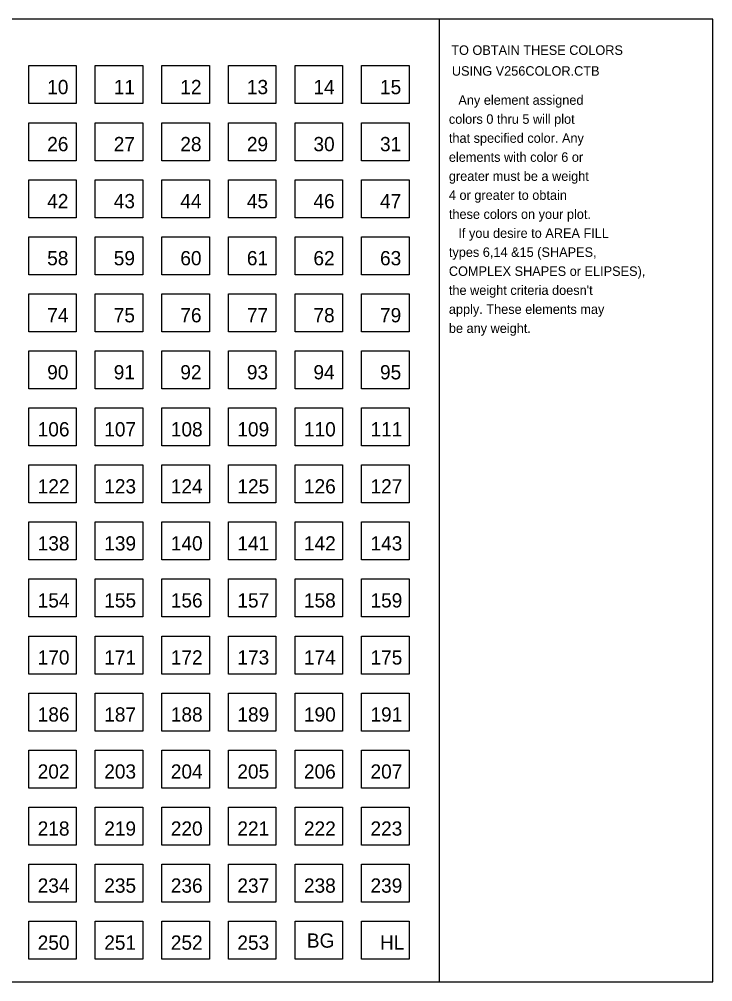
# Model space of a CAD drawing. Extents: x 11193 to 12507, y 10092 to 10555.
# Drawn here: x 12215.3 to 12507, y 10137.6 to 10542.6 of the extents above; entities that cross this region are included whole.
import ezdxf

# ---------------------------------------------------------------- set-up
doc = ezdxf.new("R2010")
doc.units = 0
for name, color, linetype in [('Level 1', 7, 'Continuous'), ('Level 3', 7, 'Continuous'), ('Level 62', 7, 'Continuous'), ('Level 63', 7, 'Continuous')]:
    doc.layers.add(name, color=color, linetype=linetype)

msp = doc.modelspace()

# ---------------------------------------------------------------- linework, layer by layer
at = {"layer": 'Level 3'}
msp.add_line((12391.98, 10137.56), (12391.98, 10542.56), dxfattribs=at)
msp.add_lwpolyline([(11926.98, 10137.56), (12506.98, 10137.56), (12506.98, 10542.56), (11926.98, 10542.56), (11926.98, 10137.56)], dxfattribs=at)
for points in [[(12219.26, 10507.04), (12219.26, 10523.04), (12239.26, 10523.04), (12239.26, 10507.04)], [(12247.26, 10507.04), (12247.26, 10523.04), (12267.26, 10523.04), (12267.26, 10507.04)], [(12275.26, 10507.04), (12275.26, 10523.04), (12295.26, 10523.04), (12295.26, 10507.04)], [(12303.26, 10507.04), (12303.26, 10523.04), (12323.26, 10523.04), (12323.26, 10507.04)], [(12331.26, 10507.04), (12331.26, 10523.04), (12351.26, 10523.04), (12351.26, 10507.04)], [(12359.26, 10507.04), (12359.26, 10523.04), (12379.26, 10523.04), (12379.26, 10507.04)], [(12219.26, 10483.04), (12219.26, 10499.04), (12239.26, 10499.04), (12239.26, 10483.04)], [(12247.26, 10483.04), (12247.26, 10499.04), (12267.26, 10499.04), (12267.26, 10483.04)], [(12275.26, 10483.04), (12275.26, 10499.04), (12295.26, 10499.04), (12295.26, 10483.04)], [(12303.26, 10483.04), (12303.26, 10499.04), (12323.26, 10499.04), (12323.26, 10483.04)], [(12331.26, 10483.04), (12331.26, 10499.04), (12351.26, 10499.04), (12351.26, 10483.04)], [(12359.26, 10483.04), (12359.26, 10499.04), (12379.26, 10499.04), (12379.26, 10483.04)], [(12219.26, 10459.04), (12219.26, 10475.04), (12239.26, 10475.04), (12239.26, 10459.04)], [(12247.26, 10459.04), (12247.26, 10475.04), (12267.26, 10475.04), (12267.26, 10459.04)], [(12275.26, 10459.04), (12275.26, 10475.04), (12295.26, 10475.04), (12295.26, 10459.04)], [(12303.26, 10459.04), (12303.26, 10475.04), (12323.26, 10475.04), (12323.26, 10459.04)], [(12331.26, 10459.04), (12331.26, 10475.04), (12351.26, 10475.04), (12351.26, 10459.04)], [(12359.26, 10459.04), (12359.26, 10475.04), (12379.26, 10475.04), (12379.26, 10459.04)], [(12219.26, 10435.04), (12219.26, 10451.04), (12239.26, 10451.04), (12239.26, 10435.04)], [(12247.26, 10435.04), (12247.26, 10451.04), (12267.26, 10451.04), (12267.26, 10435.04)], [(12275.26, 10435.04), (12275.26, 10451.04), (12295.26, 10451.04), (12295.26, 10435.04)], [(12303.26, 10435.04), (12303.26, 10451.04), (12323.26, 10451.04), (12323.26, 10435.04)], [(12331.26, 10435.04), (12331.26, 10451.04), (12351.26, 10451.04), (12351.26, 10435.04)], [(12359.26, 10435.04), (12359.26, 10451.04), (12379.26, 10451.04), (12379.26, 10435.04)], [(12219.26, 10411.04), (12219.26, 10427.04), (12239.26, 10427.04), (12239.26, 10411.04)], [(12247.26, 10411.04), (12247.26, 10427.04), (12267.26, 10427.04), (12267.26, 10411.04)], [(12275.26, 10411.04), (12275.26, 10427.04), (12295.26, 10427.04), (12295.26, 10411.04)], [(12303.26, 10411.04), (12303.26, 10427.04), (12323.26, 10427.04), (12323.26, 10411.04)], [(12331.26, 10411.04), (12331.26, 10427.04), (12351.26, 10427.04), (12351.26, 10411.04)], [(12359.26, 10411.04), (12359.26, 10427.04), (12379.26, 10427.04), (12379.26, 10411.04)], [(12219.26, 10387.04), (12219.26, 10403.04), (12239.26, 10403.04), (12239.26, 10387.04)], [(12247.26, 10387.04), (12247.26, 10403.04), (12267.26, 10403.04), (12267.26, 10387.04)], [(12275.26, 10387.04), (12275.26, 10403.04), (12295.26, 10403.04), (12295.26, 10387.04)], [(12303.26, 10387.04), (12303.26, 10403.04), (12323.26, 10403.04), (12323.26, 10387.04)], [(12331.26, 10387.04), (12331.26, 10403.04), (12351.26, 10403.04), (12351.26, 10387.04)], [(12359.26, 10387.04), (12359.26, 10403.04), (12379.26, 10403.04), (12379.26, 10387.04)], [(12219.26, 10363.04), (12219.26, 10379.04), (12239.26, 10379.04), (12239.26, 10363.04)], [(12247.26, 10363.04), (12247.26, 10379.04), (12267.26, 10379.04), (12267.26, 10363.04)], [(12275.26, 10363.04), (12275.26, 10379.04), (12295.26, 10379.04), (12295.26, 10363.04)], [(12303.26, 10363.04), (12303.26, 10379.04), (12323.26, 10379.04), (12323.26, 10363.04)], [(12331.26, 10363.04), (12331.26, 10379.04), (12351.26, 10379.04), (12351.26, 10363.04)], [(12359.26, 10363.04), (12359.26, 10379.04), (12379.26, 10379.04), (12379.26, 10363.04)], [(12219.26, 10339.04), (12219.26, 10355.04), (12239.26, 10355.04), (12239.26, 10339.04)], [(12247.26, 10339.04), (12247.26, 10355.04), (12267.26, 10355.04), (12267.26, 10339.04)], [(12275.26, 10339.04), (12275.26, 10355.04), (12295.26, 10355.04), (12295.26, 10339.04)], [(12303.26, 10339.04), (12303.26, 10355.04), (12323.26, 10355.04), (12323.26, 10339.04)], [(12331.26, 10339.04), (12331.26, 10355.04), (12351.26, 10355.04), (12351.26, 10339.04)], [(12359.26, 10339.04), (12359.26, 10355.04), (12379.26, 10355.04), (12379.26, 10339.04)], [(12219.26, 10315.04), (12219.26, 10331.04), (12239.26, 10331.04), (12239.26, 10315.04)], [(12247.26, 10315.04), (12247.26, 10331.04), (12267.26, 10331.04), (12267.26, 10315.04)], [(12275.26, 10315.04), (12275.26, 10331.04), (12295.26, 10331.04), (12295.26, 10315.04)], [(12303.26, 10315.04), (12303.26, 10331.04), (12323.26, 10331.04), (12323.26, 10315.04)], [(12331.26, 10315.04), (12331.26, 10331.04), (12351.26, 10331.04), (12351.26, 10315.04)], [(12359.26, 10315.04), (12359.26, 10331.04), (12379.26, 10331.04), (12379.26, 10315.04)], [(12219.26, 10291.04), (12219.26, 10307.04), (12239.26, 10307.04), (12239.26, 10291.04)], [(12247.26, 10291.04), (12247.26, 10307.04), (12267.26, 10307.04), (12267.26, 10291.04)], [(12275.26, 10291.04), (12275.26, 10307.04), (12295.26, 10307.04), (12295.26, 10291.04)], [(12303.26, 10291.04), (12303.26, 10307.04), (12323.26, 10307.04), (12323.26, 10291.04)], [(12331.26, 10291.04), (12331.26, 10307.04), (12351.26, 10307.04), (12351.26, 10291.04)], [(12359.26, 10291.04), (12359.26, 10307.04), (12379.26, 10307.04), (12379.26, 10291.04)], [(12219.26, 10267.04), (12219.26, 10283.04), (12239.26, 10283.04), (12239.26, 10267.04)], [(12247.26, 10267.04), (12247.26, 10283.04), (12267.26, 10283.04), (12267.26, 10267.04)], [(12275.26, 10267.04), (12275.26, 10283.04), (12295.26, 10283.04), (12295.26, 10267.04)], [(12303.26, 10267.04), (12303.26, 10283.04), (12323.26, 10283.04), (12323.26, 10267.04)], [(12331.26, 10267.04), (12331.26, 10283.04), (12351.26, 10283.04), (12351.26, 10267.04)], [(12359.26, 10267.04), (12359.26, 10283.04), (12379.26, 10283.04), (12379.26, 10267.04)], [(12219.26, 10243.04), (12219.26, 10259.04), (12239.26, 10259.04), (12239.26, 10243.04)], [(12247.26, 10243.04), (12247.26, 10259.04), (12267.26, 10259.04), (12267.26, 10243.04)], [(12275.26, 10243.04), (12275.26, 10259.04), (12295.26, 10259.04), (12295.26, 10243.04)], [(12303.26, 10243.04), (12303.26, 10259.04), (12323.26, 10259.04), (12323.26, 10243.04)], [(12331.26, 10243.04), (12331.26, 10259.04), (12351.26, 10259.04), (12351.26, 10243.04)], [(12359.26, 10243.04), (12359.26, 10259.04), (12379.26, 10259.04), (12379.26, 10243.04)], [(12219.26, 10219.04), (12219.26, 10235.04), (12239.26, 10235.04), (12239.26, 10219.04)], [(12247.26, 10219.04), (12247.26, 10235.04), (12267.26, 10235.04), (12267.26, 10219.04)], [(12275.26, 10219.04), (12275.26, 10235.04), (12295.26, 10235.04), (12295.26, 10219.04)], [(12303.26, 10219.04), (12303.26, 10235.04), (12323.26, 10235.04), (12323.26, 10219.04)], [(12331.26, 10219.04), (12331.26, 10235.04), (12351.26, 10235.04), (12351.26, 10219.04)], [(12359.26, 10219.04), (12359.26, 10235.04), (12379.26, 10235.04), (12379.26, 10219.04)], [(12219.26, 10195.04), (12219.26, 10211.04), (12239.26, 10211.04), (12239.26, 10195.04)], [(12247.26, 10195.04), (12247.26, 10211.04), (12267.26, 10211.04), (12267.26, 10195.04)], [(12275.26, 10195.04), (12275.26, 10211.04), (12295.26, 10211.04), (12295.26, 10195.04)], [(12303.26, 10195.04), (12303.26, 10211.04), (12323.26, 10211.04), (12323.26, 10195.04)], [(12331.26, 10195.04), (12331.26, 10211.04), (12351.26, 10211.04), (12351.26, 10195.04)], [(12359.26, 10195.04), (12359.26, 10211.04), (12379.26, 10211.04), (12379.26, 10195.04)], [(12219.26, 10171.04), (12219.26, 10187.04), (12239.26, 10187.04), (12239.26, 10171.04)], [(12247.26, 10171.04), (12247.26, 10187.04), (12267.26, 10187.04), (12267.26, 10171.04)], [(12275.26, 10171.04), (12275.26, 10187.04), (12295.26, 10187.04), (12295.26, 10171.04)], [(12303.26, 10171.04), (12303.26, 10187.04), (12323.26, 10187.04), (12323.26, 10171.04)], [(12331.26, 10171.04), (12331.26, 10187.04), (12351.26, 10187.04), (12351.26, 10171.04)], [(12359.26, 10171.04), (12359.26, 10187.04), (12379.26, 10187.04), (12379.26, 10171.04)], [(12219.26, 10147.04), (12219.26, 10163.04), (12239.26, 10163.04), (12239.26, 10147.04)], [(12247.26, 10147.04), (12247.26, 10163.04), (12267.26, 10163.04), (12267.26, 10147.04)], [(12275.26, 10147.04), (12275.26, 10163.04), (12295.26, 10163.04), (12295.26, 10147.04)], [(12303.26, 10147.04), (12303.26, 10163.04), (12323.26, 10163.04), (12323.26, 10147.04)]]:
    msp.add_lwpolyline(points, close=True, dxfattribs=at)
at = {"layer": 'Level 63'}
for points in [[(12219.26, 10507.04), (12219.26, 10523.04), (12239.26, 10523.04), (12239.26, 10507.04)], [(12247.26, 10507.04), (12247.26, 10523.04), (12267.26, 10523.04), (12267.26, 10507.04)], [(12275.26, 10507.04), (12275.26, 10523.04), (12295.26, 10523.04), (12295.26, 10507.04)], [(12303.26, 10507.04), (12303.26, 10523.04), (12323.26, 10523.04), (12323.26, 10507.04)], [(12331.26, 10507.04), (12331.26, 10523.04), (12351.26, 10523.04), (12351.26, 10507.04)], [(12359.26, 10507.04), (12359.26, 10523.04), (12379.26, 10523.04), (12379.26, 10507.04)], [(12219.26, 10483.04), (12219.26, 10499.04), (12239.26, 10499.04), (12239.26, 10483.04)], [(12247.26, 10483.04), (12247.26, 10499.04), (12267.26, 10499.04), (12267.26, 10483.04)], [(12275.26, 10483.04), (12275.26, 10499.04), (12295.26, 10499.04), (12295.26, 10483.04)], [(12303.26, 10483.04), (12303.26, 10499.04), (12323.26, 10499.04), (12323.26, 10483.04)], [(12331.26, 10483.04), (12331.26, 10499.04), (12351.26, 10499.04), (12351.26, 10483.04)], [(12359.26, 10483.04), (12359.26, 10499.04), (12379.26, 10499.04), (12379.26, 10483.04)], [(12219.26, 10459.04), (12219.26, 10475.04), (12239.26, 10475.04), (12239.26, 10459.04)], [(12247.26, 10459.04), (12247.26, 10475.04), (12267.26, 10475.04), (12267.26, 10459.04)], [(12275.26, 10459.04), (12275.26, 10475.04), (12295.26, 10475.04), (12295.26, 10459.04)], [(12303.26, 10459.04), (12303.26, 10475.04), (12323.26, 10475.04), (12323.26, 10459.04)], [(12331.26, 10459.04), (12331.26, 10475.04), (12351.26, 10475.04), (12351.26, 10459.04)], [(12359.26, 10459.04), (12359.26, 10475.04), (12379.26, 10475.04), (12379.26, 10459.04)], [(12219.26, 10435.04), (12219.26, 10451.04), (12239.26, 10451.04), (12239.26, 10435.04)], [(12247.26, 10435.04), (12247.26, 10451.04), (12267.26, 10451.04), (12267.26, 10435.04)], [(12275.26, 10435.04), (12275.26, 10451.04), (12295.26, 10451.04), (12295.26, 10435.04)], [(12303.26, 10435.04), (12303.26, 10451.04), (12323.26, 10451.04), (12323.26, 10435.04)], [(12331.26, 10435.04), (12331.26, 10451.04), (12351.26, 10451.04), (12351.26, 10435.04)], [(12359.26, 10435.04), (12359.26, 10451.04), (12379.26, 10451.04), (12379.26, 10435.04)], [(12219.26, 10411.04), (12219.26, 10427.04), (12239.26, 10427.04), (12239.26, 10411.04)], [(12247.26, 10411.04), (12247.26, 10427.04), (12267.26, 10427.04), (12267.26, 10411.04)], [(12275.26, 10411.04), (12275.26, 10427.04), (12295.26, 10427.04), (12295.26, 10411.04)], [(12303.26, 10411.04), (12303.26, 10427.04), (12323.26, 10427.04), (12323.26, 10411.04)], [(12331.26, 10411.04), (12331.26, 10427.04), (12351.26, 10427.04), (12351.26, 10411.04)], [(12359.26, 10411.04), (12359.26, 10427.04), (12379.26, 10427.04), (12379.26, 10411.04)], [(12219.26, 10387.04), (12219.26, 10403.04), (12239.26, 10403.04), (12239.26, 10387.04)], [(12247.26, 10387.04), (12247.26, 10403.04), (12267.26, 10403.04), (12267.26, 10387.04)], [(12275.26, 10387.04), (12275.26, 10403.04), (12295.26, 10403.04), (12295.26, 10387.04)], [(12303.26, 10387.04), (12303.26, 10403.04), (12323.26, 10403.04), (12323.26, 10387.04)], [(12331.26, 10387.04), (12331.26, 10403.04), (12351.26, 10403.04), (12351.26, 10387.04)], [(12359.26, 10387.04), (12359.26, 10403.04), (12379.26, 10403.04), (12379.26, 10387.04)], [(12219.26, 10363.04), (12219.26, 10379.04), (12239.26, 10379.04), (12239.26, 10363.04)], [(12247.26, 10363.04), (12247.26, 10379.04), (12267.26, 10379.04), (12267.26, 10363.04)], [(12275.26, 10363.04), (12275.26, 10379.04), (12295.26, 10379.04), (12295.26, 10363.04)], [(12303.26, 10363.04), (12303.26, 10379.04), (12323.26, 10379.04), (12323.26, 10363.04)], [(12331.26, 10363.04), (12331.26, 10379.04), (12351.26, 10379.04), (12351.26, 10363.04)], [(12359.26, 10363.04), (12359.26, 10379.04), (12379.26, 10379.04), (12379.26, 10363.04)], [(12219.26, 10339.04), (12219.26, 10355.04), (12239.26, 10355.04), (12239.26, 10339.04)], [(12247.26, 10339.04), (12247.26, 10355.04), (12267.26, 10355.04), (12267.26, 10339.04)], [(12275.26, 10339.04), (12275.26, 10355.04), (12295.26, 10355.04), (12295.26, 10339.04)], [(12303.26, 10339.04), (12303.26, 10355.04), (12323.26, 10355.04), (12323.26, 10339.04)], [(12331.26, 10339.04), (12331.26, 10355.04), (12351.26, 10355.04), (12351.26, 10339.04)], [(12359.26, 10339.04), (12359.26, 10355.04), (12379.26, 10355.04), (12379.26, 10339.04)], [(12219.26, 10315.04), (12219.26, 10331.04), (12239.26, 10331.04), (12239.26, 10315.04)], [(12247.26, 10315.04), (12247.26, 10331.04), (12267.26, 10331.04), (12267.26, 10315.04)], [(12275.26, 10315.04), (12275.26, 10331.04), (12295.26, 10331.04), (12295.26, 10315.04)], [(12303.26, 10315.04), (12303.26, 10331.04), (12323.26, 10331.04), (12323.26, 10315.04)], [(12331.26, 10315.04), (12331.26, 10331.04), (12351.26, 10331.04), (12351.26, 10315.04)], [(12359.26, 10315.04), (12359.26, 10331.04), (12379.26, 10331.04), (12379.26, 10315.04)], [(12219.26, 10291.04), (12219.26, 10307.04), (12239.26, 10307.04), (12239.26, 10291.04)], [(12247.26, 10291.04), (12247.26, 10307.04), (12267.26, 10307.04), (12267.26, 10291.04)], [(12275.26, 10291.04), (12275.26, 10307.04), (12295.26, 10307.04), (12295.26, 10291.04)], [(12303.26, 10291.04), (12303.26, 10307.04), (12323.26, 10307.04), (12323.26, 10291.04)], [(12331.26, 10291.04), (12331.26, 10307.04), (12351.26, 10307.04), (12351.26, 10291.04)], [(12359.26, 10291.04), (12359.26, 10307.04), (12379.26, 10307.04), (12379.26, 10291.04)], [(12219.26, 10267.04), (12219.26, 10283.04), (12239.26, 10283.04), (12239.26, 10267.04)], [(12247.26, 10267.04), (12247.26, 10283.04), (12267.26, 10283.04), (12267.26, 10267.04)], [(12275.26, 10267.04), (12275.26, 10283.04), (12295.26, 10283.04), (12295.26, 10267.04)], [(12303.26, 10267.04), (12303.26, 10283.04), (12323.26, 10283.04), (12323.26, 10267.04)], [(12331.26, 10267.04), (12331.26, 10283.04), (12351.26, 10283.04), (12351.26, 10267.04)], [(12359.26, 10267.04), (12359.26, 10283.04), (12379.26, 10283.04), (12379.26, 10267.04)], [(12219.26, 10243.04), (12219.26, 10259.04), (12239.26, 10259.04), (12239.26, 10243.04)], [(12247.26, 10243.04), (12247.26, 10259.04), (12267.26, 10259.04), (12267.26, 10243.04)], [(12275.26, 10243.04), (12275.26, 10259.04), (12295.26, 10259.04), (12295.26, 10243.04)], [(12303.26, 10243.04), (12303.26, 10259.04), (12323.26, 10259.04), (12323.26, 10243.04)], [(12331.26, 10243.04), (12331.26, 10259.04), (12351.26, 10259.04), (12351.26, 10243.04)], [(12359.26, 10243.04), (12359.26, 10259.04), (12379.26, 10259.04), (12379.26, 10243.04)], [(12219.26, 10219.04), (12219.26, 10235.04), (12239.26, 10235.04), (12239.26, 10219.04)], [(12247.26, 10219.04), (12247.26, 10235.04), (12267.26, 10235.04), (12267.26, 10219.04)], [(12275.26, 10219.04), (12275.26, 10235.04), (12295.26, 10235.04), (12295.26, 10219.04)], [(12303.26, 10219.04), (12303.26, 10235.04), (12323.26, 10235.04), (12323.26, 10219.04)], [(12331.26, 10219.04), (12331.26, 10235.04), (12351.26, 10235.04), (12351.26, 10219.04)], [(12359.26, 10219.04), (12359.26, 10235.04), (12379.26, 10235.04), (12379.26, 10219.04)], [(12219.26, 10195.04), (12219.26, 10211.04), (12239.26, 10211.04), (12239.26, 10195.04)], [(12247.26, 10195.04), (12247.26, 10211.04), (12267.26, 10211.04), (12267.26, 10195.04)], [(12275.26, 10195.04), (12275.26, 10211.04), (12295.26, 10211.04), (12295.26, 10195.04)], [(12303.26, 10195.04), (12303.26, 10211.04), (12323.26, 10211.04), (12323.26, 10195.04)], [(12331.26, 10195.04), (12331.26, 10211.04), (12351.26, 10211.04), (12351.26, 10195.04)], [(12359.26, 10195.04), (12359.26, 10211.04), (12379.26, 10211.04), (12379.26, 10195.04)], [(12219.26, 10171.04), (12219.26, 10187.04), (12239.26, 10187.04), (12239.26, 10171.04)], [(12247.26, 10171.04), (12247.26, 10187.04), (12267.26, 10187.04), (12267.26, 10171.04)], [(12275.26, 10171.04), (12275.26, 10187.04), (12295.26, 10187.04), (12295.26, 10171.04)], [(12303.26, 10171.04), (12303.26, 10187.04), (12323.26, 10187.04), (12323.26, 10171.04)], [(12331.26, 10171.04), (12331.26, 10187.04), (12351.26, 10187.04), (12351.26, 10171.04)], [(12359.26, 10171.04), (12359.26, 10187.04), (12379.26, 10187.04), (12379.26, 10171.04)], [(12219.26, 10147.04), (12219.26, 10163.04), (12239.26, 10163.04), (12239.26, 10147.04)], [(12247.26, 10147.04), (12247.26, 10163.04), (12267.26, 10163.04), (12267.26, 10147.04)], [(12275.26, 10147.04), (12275.26, 10163.04), (12295.26, 10163.04), (12295.26, 10147.04)], [(12303.26, 10147.04), (12303.26, 10163.04), (12323.26, 10163.04), (12323.26, 10147.04)], [(12331.26, 10147.04), (12331.26, 10163.04), (12351.26, 10163.04), (12351.26, 10147.04)], [(12359.26, 10147.04), (12359.26, 10163.04), (12379.26, 10163.04), (12379.26, 10147.04)]]:
    msp.add_lwpolyline(points, close=True, dxfattribs=at)

# ---------------------------------------------------------------- texts
at = {"layer": 'Level 1'}
for s, p in [('TO OBTAIN THESE COLORS', (12396.98, 10527.56)), ('USING V256COLOR.CTB', (12397.24, 10518.8)), ('Any element assigned', (12399.98, 10506.56)), ('colors 0 thru 5 will plot', (12395.98, 10498.56)), ('that specified color. Any', (12395.98, 10490.56)), ('elements with color 6 or', (12395.98, 10482.56)), ('greater must be a weight', (12395.98, 10474.56)), ('4 or greater to obtain', (12395.98, 10466.56)), ('these colors on your plot.', (12395.98, 10458.56)), ('If you desire to AREA FILL', (12399.98, 10450.56)), ('types 6,14 &15 (SHAPES,', (12395.98, 10442.56)), ('COMPLEX SHAPES or ELIPSES),', (12395.98, 10434.56)), ("the weight criteria doesn't", (12395.98, 10426.56)), ('apply. These elements may', (12395.98, 10418.56)), ('be any weight.', (12395.98, 10410.56))]:
    msp.add_text(s, height=4, dxfattribs=at).set_placement(p)
at = {"layer": 'Level 62'}
for s, p in [('10', (12227.01, 10511.03)), ('11', (12255.01, 10511.03)), ('12', (12283.01, 10511.03)), ('13', (12311.01, 10511.03)), ('14', (12339.01, 10511.03)), ('15', (12367.01, 10511.03)), ('26', (12227.01, 10487.03)), ('27', (12255.01, 10487.03)), ('28', (12283.01, 10487.03)), ('29', (12311.01, 10487.03)), ('30', (12339.01, 10487.03)), ('31', (12367.01, 10487.03)), ('42', (12227.01, 10463.03)), ('43', (12255.01, 10463.03)), ('44', (12283.01, 10463.03)), ('45', (12311.01, 10463.03)), ('46', (12339.01, 10463.03)), ('47', (12367.01, 10463.03)), ('58', (12227.01, 10439.03)), ('59', (12255.01, 10439.03)), ('60', (12283.01, 10439.03)), ('61', (12311.01, 10439.03)), ('62', (12339.01, 10439.03)), ('63', (12367.01, 10439.03)), ('74', (12227.01, 10415.03)), ('75', (12255.01, 10415.03)), ('76', (12283.01, 10415.03)), ('77', (12311.01, 10415.03)), ('78', (12339.01, 10415.03)), ('79', (12367.01, 10415.03)), ('90', (12227.01, 10391.03)), ('91', (12255.01, 10391.03)), ('92', (12283.01, 10391.03)), ('93', (12311.01, 10391.03)), ('94', (12339.01, 10391.03)), ('95', (12367.01, 10391.03)), ('106', (12223.01, 10367.03)), ('107', (12251.01, 10367.03)), ('108', (12279.01, 10367.03)), ('109', (12307.01, 10367.03)), ('110', (12335.01, 10367.03)), ('111', (12363.01, 10367.03)), ('122', (12223.01, 10343.03)), ('123', (12251.01, 10343.03)), ('124', (12279.01, 10343.03)), ('125', (12307.01, 10343.03)), ('126', (12335.01, 10343.03)), ('127', (12363.01, 10343.03)), ('138', (12223.01, 10319.03)), ('139', (12251.01, 10319.03)), ('140', (12279.01, 10319.03)), ('141', (12307.01, 10319.03)), ('142', (12335.01, 10319.03)), ('143', (12363.01, 10319.03)), ('154', (12223.01, 10295.03)), ('155', (12251.01, 10295.03)), ('156', (12279.01, 10295.03)), ('157', (12307.01, 10295.03)), ('158', (12335.01, 10295.03)), ('159', (12363.01, 10295.03)), ('170', (12223.01, 10271.03)), ('171', (12251.01, 10271.03)), ('172', (12279.01, 10271.03)), ('173', (12307.01, 10271.03)), ('174', (12335.01, 10271.03)), ('175', (12363.01, 10271.03)), ('186', (12223.01, 10247.03)), ('187', (12251.01, 10247.03)), ('188', (12279.01, 10247.03)), ('189', (12307.01, 10247.03)), ('190', (12335.01, 10247.03)), ('191', (12363.01, 10247.03)), ('202', (12223.01, 10223.03)), ('203', (12251.01, 10223.03)), ('204', (12279.01, 10223.03)), ('205', (12307.01, 10223.03)), ('206', (12335.01, 10223.03)), ('207', (12363.01, 10223.03)), ('218', (12223.01, 10199.03)), ('219', (12251.01, 10199.03)), ('220', (12279.01, 10199.03)), ('221', (12307.01, 10199.03)), ('222', (12335.01, 10199.03)), ('223', (12363.01, 10199.03)), ('234', (12223.01, 10175.03)), ('235', (12251.01, 10175.03)), ('236', (12279.01, 10175.03)), ('237', (12307.01, 10175.03)), ('238', (12335.01, 10175.03)), ('239', (12363.01, 10175.03)), ('BG', (12336.23, 10151.9)), ('250', (12223.01, 10151.03)), ('251', (12251.01, 10151.03)), ('252', (12279.01, 10151.03)), ('253', (12307.01, 10151.03)), ('HL', (12367.01, 10151.03))]:
    msp.add_text(s, height=6, dxfattribs=at).set_placement(p)

doc.saveas('drawing.dxf')
